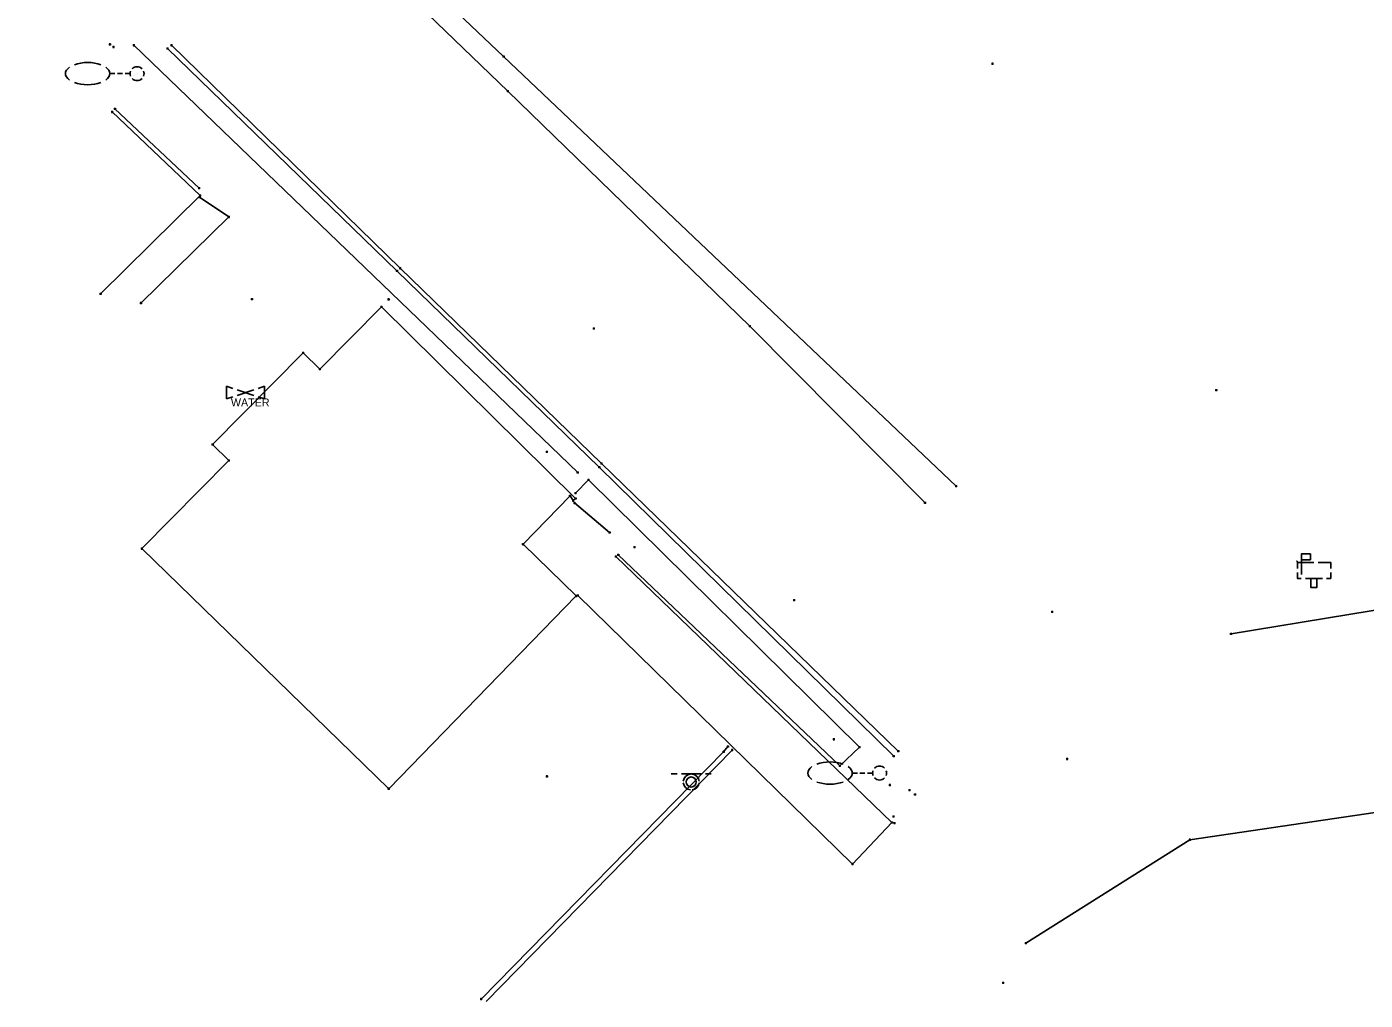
# Model space of a CAD drawing. Extents: x 1954856 to 2011933, y 399149 to 426294.
# Drawn here: x 2005154.1 to 2005312.9, y 406133.7 to 406249.2 of the extents above; entities that cross this region are included whole.
import ezdxf

# ---------------------------------------------------------------- set-up
doc = ezdxf.new("R2010")
doc.units = 0
for name, color, linetype in [('Building_ep', 7, 'Continuous'), ('CGBack_ep', 7, 'Continuous'), ('Driveway_ep', 7, 'Continuous'), ('Fence_ep', 7, 'Continuous'), ('Luminaire_ep', 7, 'Continuous'), ('Mailbox_ep', 7, 'Continuous'), ('PointLocator_ep', 7, 'Continuous'), ('ShrubHedge_ep', 7, 'Continuous'), ('SidewalkFront_ep', 7, 'Continuous'), ('SignSingle_ep', 7, 'Continuous'), ('Stairs_ep', 7, 'Continuous'), ('ValveWater_ep', 7, 'Continuous')]:
    doc.layers.add(name, color=color, linetype=linetype)

# ---------------------------------------------------------------- blocks, each defined once
blk = doc.blocks.new('SURVPN-CROSS-')
at = {"layer": 'PointLocator_ep'}
for p, q in [((0.125, 0), (-0.125, 0)), ((0, -0.125), (0, 0.125)), ((0, 0), (0, 0))]:
    blk.add_line(p, q, dxfattribs=at)

msp = doc.modelspace()

# ---------------------------------------------------------------- linework, layer by layer
at = {"layer": 'Building_ep'}
msp.add_lwpolyline([(2005197.06, 406158.83), (2005219.31, 406181.7), (2005213, 406187.84), (2005218.58, 406193.57), (2005218.95, 406193.02), (2005219.24, 406193.27), (2005196.21, 406216), (2005188.9, 406208.6), (2005186.91, 406210.57), (2005176.16, 406199.68), (2005178.08, 406197.78), (2005167.76, 406187.32)], close=True, dxfattribs=at)
at = {"layer": 'CGBack_ep'}
for p, q in [((2005198.03, 406220.28), (2005170.82, 406246.68)), ((2005164.57, 406239.52), (2005174.58, 406230.08)), ((2005222.05, 406196.98), (2005198.03, 406220.28)), ((2005256.98, 406162.69), (2005222.05, 406196.98))]:
    msp.add_line(p, q, dxfattribs=at)
msp.add_lwpolyline([(2005237.31, 406163.84), (2005236.8, 406163.22), (2005208.02, 406133.88)], dxfattribs=at)
at = {"layer": 'Driveway_ep'}
for p, q in [((2005154.1, 406296.53), (2005211.2, 406241.61)), ((2005198.4, 406220.59), (2005171.28, 406247.05)), ((2005211.2, 406241.61), (2005239.9, 406213.7)), ((2005164.25, 406239.14), (2005174.68, 406229.21)), ((2005174.68, 406229.21), (2005162.87, 406217.56)), ((2005222.31, 406197.43), (2005198.4, 406220.59)), ((2005239.9, 406213.7), (2005260.7, 406192.74)), ((2005257.53, 406163.3), (2005222.31, 406197.43)), ((2005297.01, 406177.21), (2005316.96, 406180.47)), ((2005208.64, 406133.6), (2005237.83, 406163.42)), ((2005317.28, 406156.5), (2005292.13, 406152.78)), ((2005292.13, 406152.78), (2005272.68, 406140.52))]:
    msp.add_line(p, q, dxfattribs=at)
at = {"layer": 'Fence_ep'}
msp.add_lwpolyline([(2005156.64, 406297), (2005210.69, 406245.71), (2005264.38, 406194.73)], dxfattribs=at)
at = {"layer": 'Luminaire_ep'}
for p, q in [((2005164.57, 406243.68), (2005163.97, 406243.68)), ((2005165.47, 406243.68), (2005164.87, 406243.68)), ((2005166.37, 406243.68), (2005165.77, 406243.68)), ((2005167.2, 406243.68), (2005167.2, 406243.68)), ((2005252.67, 406160.69), (2005252.07, 406160.69)), ((2005253.57, 406160.69), (2005252.97, 406160.69)), ((2005254.47, 406160.69), (2005253.87, 406160.69)), ((2005255.3, 406160.69), (2005255.3, 406160.69))]:
    msp.add_line(p, q, dxfattribs=at)
for centre, start, end in [((2005167.2, 406243.68), 159.9115, 200.0885), ((2005167.2, 406243.68), 45, 135), ((2005167.2, 406243.68), 339.9115, 20.0885), ((2005167.2, 406243.68), 225, 315), ((2005255.3, 406160.69), 45, 135), ((2005255.3, 406160.69), 159.9115, 200.0885), ((2005255.3, 406160.69), 225, 315), ((2005255.3, 406160.69), 339.9115, 20.0885)]:
    msp.add_arc(centre, 0.825, start, end, dxfattribs=at)
for centre, start_param, end_param in [((2005161.33, 406243.68), 5.668326, 6.898045), ((2005161.33, 406243.68), 4.075781, 5.348997), ((2005161.33, 406243.68), 2.526733, 3.756452), ((2005161.33, 406243.68), 0.934187, 2.207405), ((2005249.43, 406160.69), 5.668326, 6.898045), ((2005249.43, 406160.69), 4.075781, 5.348997), ((2005249.43, 406160.69), 2.526733, 3.756452), ((2005249.43, 406160.69), 0.934187, 2.207405)]:
    msp.add_ellipse(centre, major_axis=(-2.64, 0), ratio=0.5, start_param=start_param, end_param=end_param, dxfattribs=at)
at = {"layer": 'Mailbox_ep'}
for p, q in [((2005304.9, 406185.69), (2005304.9, 406184.98)), ((2005306.85, 406185.69), (2005304.9, 406185.69)), ((2005305.36, 406184.27), (2005305.36, 406186.01)), ((2005305.36, 406186.01), (2005306.35, 406186.01)), ((2005308.85, 406185.69), (2005308.85, 406184.98)), ((2005305.85, 406183.78), (2005306.35, 406183.78)), ((2005306.35, 406183.78), (2005307.85, 406183.78)), ((2005308.85, 406184.48), (2005308.85, 406183.78)), ((2005306.83, 406182.7), (2005306.83, 406182.7))]:
    msp.add_line(p, q, dxfattribs=at)
for points in [[(2005306.35, 406186.7), (2005305.36, 406186.7), (2005305.36, 406186.01)], [(2005306.35, 406186.01), (2005306.44, 406186.01), (2005306.44, 406186.7), (2005306.35, 406186.7)], [(2005304.78, 406185.82), (2005304.86, 406185.82), (2005304.9, 406185.64)], [(2005308.85, 406185.23), (2005308.85, 406185.69), (2005307.35, 406185.69)], [(2005304.9, 406184.48), (2005304.9, 406183.78), (2005305.35, 406183.78)], [(2005306.49, 406183.78), (2005306.49, 406182.7), (2005307.18, 406182.7), (2005307.18, 406183.78)], [(2005308.35, 406183.78), (2005308.85, 406183.78), (2005308.85, 406184.23)]]:
    msp.add_lwpolyline(points, dxfattribs=at)
at = {"layer": 'PointLocator_ep'}
for p, q in [((2005164.11, 406247.15), (2005163.86, 406247.15)), ((2005163.98, 406247.03), (2005163.98, 406247.28)), ((2005163.98, 406247.15), (2005163.98, 406247.15)), ((2005164.4, 406246.72), (2005164.4, 406246.97)), ((2005166.94, 406247.04), (2005166.69, 406247.04)), ((2005166.82, 406246.91), (2005166.82, 406247.16)), ((2005166.82, 406247.04), (2005166.82, 406247.04)), ((2005171.41, 406247.05), (2005171.16, 406247.05)), ((2005171.28, 406246.92), (2005171.28, 406247.17)), ((2005171.28, 406247.05), (2005171.28, 406247.05)), ((2005164.53, 406246.85), (2005164.28, 406246.85)), ((2005164.4, 406246.85), (2005164.4, 406246.85)), ((2005170.94, 406246.68), (2005170.69, 406246.68)), ((2005170.82, 406246.55), (2005170.82, 406246.8)), ((2005170.82, 406246.68), (2005170.82, 406246.68)), ((2005210.82, 406245.71), (2005210.57, 406245.71)), ((2005210.69, 406245.58), (2005210.69, 406245.83)), ((2005210.69, 406245.71), (2005210.69, 406245.71)), ((2005268.83, 406244.86), (2005268.58, 406244.86)), ((2005268.7, 406244.74), (2005268.7, 406244.99)), ((2005268.7, 406244.86), (2005268.7, 406244.86)), ((2005211.32, 406241.61), (2005211.07, 406241.61)), ((2005211.2, 406241.48), (2005211.2, 406241.73)), ((2005211.2, 406241.61), (2005211.2, 406241.61)), ((2005164.37, 406239.14), (2005164.12, 406239.14)), ((2005164.25, 406239.01), (2005164.25, 406239.26)), ((2005164.25, 406239.14), (2005164.25, 406239.14)), ((2005164.7, 406239.52), (2005164.45, 406239.52)), ((2005164.57, 406239.39), (2005164.57, 406239.64)), ((2005164.57, 406239.52), (2005164.57, 406239.52)), ((2005174.7, 406230.08), (2005174.45, 406230.08)), ((2005174.58, 406229.96), (2005174.58, 406230.21)), ((2005174.58, 406230.08), (2005174.58, 406230.08)), ((2005174.75, 406229.02), (2005174.5, 406229.02)), ((2005174.81, 406229.21), (2005174.56, 406229.21)), ((2005174.62, 406228.9), (2005174.62, 406229.15)), ((2005174.62, 406229.02), (2005174.62, 406229.02)), ((2005174.68, 406229.09), (2005174.68, 406229.34)), ((2005174.68, 406229.21), (2005174.68, 406229.21)), ((2005178.21, 406226.68), (2005177.96, 406226.68)), ((2005178.09, 406226.55), (2005178.09, 406226.8)), ((2005178.09, 406226.68), (2005178.09, 406226.68)), ((2005198.16, 406220.28), (2005197.91, 406220.28)), ((2005198.03, 406220.16), (2005198.03, 406220.41)), ((2005198.03, 406220.28), (2005198.03, 406220.28)), ((2005198.53, 406220.59), (2005198.28, 406220.59)), ((2005198.4, 406220.46), (2005198.4, 406220.71)), ((2005198.4, 406220.59), (2005198.4, 406220.59)), ((2005163, 406217.56), (2005162.75, 406217.56)), ((2005162.87, 406217.43), (2005162.87, 406217.68)), ((2005162.87, 406217.56), (2005162.87, 406217.56)), ((2005180.96, 406216.93), (2005180.71, 406216.93)), ((2005180.83, 406216.8), (2005180.83, 406217.05)), ((2005180.83, 406216.93), (2005180.83, 406216.93)), ((2005197.17, 406216.9), (2005196.92, 406216.9)), ((2005197.04, 406216.78), (2005197.04, 406217.03)), ((2005197.04, 406216.9), (2005197.04, 406216.9)), ((2005167.78, 406216.46), (2005167.53, 406216.46)), ((2005167.66, 406216.34), (2005167.66, 406216.59)), ((2005167.66, 406216.46), (2005167.66, 406216.46)), ((2005196.33, 406216), (2005196.08, 406216)), ((2005196.21, 406215.88), (2005196.21, 406216.13)), ((2005196.21, 406216), (2005196.21, 406216)), ((2005240.03, 406213.7), (2005239.78, 406213.7)), ((2005239.9, 406213.58), (2005239.9, 406213.83)), ((2005239.9, 406213.7), (2005239.9, 406213.7)), ((2005187.03, 406210.57), (2005186.78, 406210.57)), ((2005186.91, 406210.44), (2005186.91, 406210.69)), ((2005186.91, 406210.57), (2005186.91, 406210.57)), ((2005189.02, 406208.6), (2005188.77, 406208.6)), ((2005188.9, 406208.48), (2005188.9, 406208.73)), ((2005188.9, 406208.6), (2005188.9, 406208.6)), ((2005295.39, 406206.12), (2005295.14, 406206.12)), ((2005295.26, 406206), (2005295.26, 406206.25)), ((2005295.26, 406206.12), (2005295.26, 406206.12)), ((2005176.29, 406199.68), (2005176.04, 406199.68)), ((2005176.16, 406199.55), (2005176.16, 406199.8)), ((2005176.16, 406199.68), (2005176.16, 406199.68)), ((2005178.21, 406197.78), (2005177.96, 406197.78)), ((2005178.08, 406197.66), (2005178.08, 406197.91)), ((2005178.08, 406197.78), (2005178.08, 406197.78)), ((2005215.95, 406198.8), (2005215.7, 406198.8)), ((2005215.82, 406198.67), (2005215.82, 406198.92)), ((2005215.82, 406198.8), (2005215.82, 406198.8)), ((2005219.61, 406196.34), (2005219.36, 406196.34)), ((2005219.49, 406196.22), (2005219.49, 406196.47)), ((2005219.49, 406196.34), (2005219.49, 406196.34)), ((2005222.18, 406196.98), (2005221.93, 406196.98)), ((2005222.05, 406196.85), (2005222.05, 406197.1)), ((2005222.05, 406196.98), (2005222.05, 406196.98)), ((2005222.43, 406197.43), (2005222.18, 406197.43)), ((2005222.31, 406197.3), (2005222.31, 406197.55)), ((2005222.31, 406197.43), (2005222.31, 406197.43)), ((2005220.89, 406195.5), (2005220.64, 406195.5)), ((2005220.77, 406195.37), (2005220.77, 406195.62)), ((2005220.77, 406195.5), (2005220.77, 406195.5)), ((2005264.51, 406194.73), (2005264.26, 406194.73)), ((2005264.38, 406194.6), (2005264.38, 406194.85)), ((2005264.38, 406194.73), (2005264.38, 406194.73)), ((2005218.7, 406193.57), (2005218.45, 406193.57)), ((2005218.58, 406193.45), (2005218.58, 406193.7)), ((2005218.58, 406193.57), (2005218.58, 406193.57)), ((2005219.08, 406193.02), (2005218.83, 406193.02)), ((2005218.95, 406192.89), (2005218.95, 406193.14)), ((2005218.95, 406193.02), (2005218.95, 406193.02)), ((2005219.35, 406193.9), (2005219.1, 406193.9)), ((2005219.37, 406193.27), (2005219.12, 406193.27)), ((2005219.23, 406193.78), (2005219.23, 406194.03)), ((2005219.23, 406193.9), (2005219.23, 406193.9)), ((2005219.24, 406193.14), (2005219.24, 406193.39)), ((2005219.24, 406193.27), (2005219.24, 406193.27)), ((2005219.23, 406192.74), (2005218.98, 406192.74)), ((2005219.1, 406192.61), (2005219.1, 406192.86)), ((2005219.1, 406192.74), (2005219.1, 406192.74)), ((2005260.82, 406192.74), (2005260.57, 406192.74)), ((2005260.7, 406192.62), (2005260.7, 406192.87)), ((2005260.7, 406192.74), (2005260.7, 406192.74)), ((2005223.4, 406189.25), (2005223.15, 406189.25)), ((2005223.27, 406189.12), (2005223.27, 406189.37)), ((2005223.27, 406189.25), (2005223.27, 406189.25)), ((2005167.88, 406187.32), (2005167.63, 406187.32)), ((2005167.76, 406187.19), (2005167.76, 406187.44)), ((2005167.76, 406187.32), (2005167.76, 406187.32)), ((2005213.12, 406187.84), (2005212.87, 406187.84)), ((2005213, 406187.71), (2005213, 406187.96)), ((2005213, 406187.84), (2005213, 406187.84)), ((2005224.3, 406186.46), (2005224.3, 406186.71)), ((2005226.35, 406187.48), (2005226.1, 406187.48)), ((2005226.22, 406187.36), (2005226.22, 406187.61)), ((2005226.22, 406187.48), (2005226.22, 406187.48)), ((2005224.13, 406186.38), (2005223.88, 406186.38)), ((2005224.01, 406186.25), (2005224.01, 406186.5)), ((2005224.01, 406186.38), (2005224.01, 406186.38)), ((2005224.43, 406186.58), (2005224.18, 406186.58)), ((2005224.3, 406186.58), (2005224.3, 406186.58)), ((2005219.5, 406181.63), (2005219.5, 406181.88)), ((2005219.43, 406181.7), (2005219.18, 406181.7)), ((2005219.31, 406181.58), (2005219.31, 406181.83)), ((2005219.31, 406181.7), (2005219.31, 406181.7)), ((2005219.62, 406181.75), (2005219.37, 406181.75)), ((2005219.5, 406181.75), (2005219.5, 406181.75)), ((2005245.3, 406181.19), (2005245.05, 406181.19)), ((2005245.18, 406181.07), (2005245.18, 406181.32)), ((2005245.18, 406181.19), (2005245.18, 406181.19)), ((2005275.91, 406179.81), (2005275.66, 406179.81)), ((2005275.79, 406179.69), (2005275.79, 406179.94)), ((2005275.79, 406179.81), (2005275.79, 406179.81)), ((2005297.14, 406177.21), (2005296.89, 406177.21)), ((2005297.01, 406177.08), (2005297.01, 406177.33)), ((2005297.01, 406177.21), (2005297.01, 406177.21)), ((2005249.99, 406164.7), (2005249.74, 406164.7)), ((2005249.86, 406164.57), (2005249.86, 406164.82)), ((2005249.86, 406164.7), (2005249.86, 406164.7)), ((2005236.93, 406163.22), (2005236.68, 406163.22)), ((2005236.8, 406163.09), (2005236.8, 406163.34)), ((2005236.8, 406163.22), (2005236.8, 406163.22)), ((2005237.44, 406163.84), (2005237.19, 406163.84)), ((2005237.31, 406163.71), (2005237.31, 406163.96)), ((2005237.31, 406163.84), (2005237.31, 406163.84)), ((2005237.95, 406163.42), (2005237.7, 406163.42)), ((2005237.83, 406163.3), (2005237.83, 406163.55)), ((2005237.83, 406163.42), (2005237.83, 406163.42)), ((2005253.06, 406163.76), (2005252.81, 406163.76)), ((2005252.93, 406163.64), (2005252.93, 406163.89)), ((2005252.93, 406163.76), (2005252.93, 406163.76)), ((2005256.98, 406162.56), (2005256.98, 406162.81)), ((2005257.66, 406163.3), (2005257.41, 406163.3)), ((2005257.53, 406163.17), (2005257.53, 406163.42)), ((2005257.53, 406163.3), (2005257.53, 406163.3)), ((2005250.72, 406161.55), (2005250.47, 406161.55)), ((2005250.59, 406161.42), (2005250.59, 406161.67)), ((2005250.59, 406161.55), (2005250.59, 406161.55)), ((2005257.1, 406162.69), (2005256.85, 406162.69)), ((2005256.98, 406162.69), (2005256.98, 406162.69)), ((2005215.96, 406160.3), (2005215.71, 406160.3)), ((2005215.83, 406160.18), (2005215.83, 406160.43)), ((2005215.83, 406160.3), (2005215.83, 406160.3)), ((2005197.18, 406158.83), (2005196.93, 406158.83)), ((2005197.06, 406158.71), (2005197.06, 406158.96)), ((2005197.06, 406158.83), (2005197.06, 406158.83)), ((2005256.66, 406159.27), (2005256.41, 406159.27)), ((2005256.53, 406159.15), (2005256.53, 406159.4)), ((2005256.53, 406159.27), (2005256.53, 406159.27)), ((2005258.98, 406158.67), (2005258.73, 406158.67)), ((2005258.86, 406158.54), (2005258.86, 406158.79)), ((2005258.86, 406158.67), (2005258.86, 406158.67)), ((2005259.64, 406158.16), (2005259.39, 406158.16)), ((2005259.52, 406158.03), (2005259.52, 406158.28)), ((2005259.52, 406158.16), (2005259.52, 406158.16)), ((2005256.78, 406154.69), (2005256.78, 406154.94)), ((2005257.07, 406155.52), (2005256.82, 406155.52)), ((2005256.95, 406155.4), (2005256.95, 406155.65)), ((2005256.95, 406155.52), (2005256.95, 406155.52)), ((2005257.07, 406154.61), (2005257.07, 406154.86)), ((2005256.91, 406154.81), (2005256.66, 406154.81)), ((2005256.78, 406154.81), (2005256.78, 406154.81)), ((2005257.19, 406154.74), (2005256.94, 406154.74)), ((2005257.07, 406154.74), (2005257.07, 406154.74)), ((2005292.25, 406152.78), (2005292, 406152.78)), ((2005292.13, 406152.66), (2005292.13, 406152.91)), ((2005292.13, 406152.78), (2005292.13, 406152.78)), ((2005252.23, 406149.89), (2005251.98, 406149.89)), ((2005252.11, 406149.77), (2005252.11, 406150.02)), ((2005252.11, 406149.89), (2005252.11, 406149.89)), ((2005272.68, 406140.39), (2005272.68, 406140.64)), ((2005272.8, 406140.52), (2005272.55, 406140.52)), ((2005272.68, 406140.52), (2005272.68, 406140.52)), ((2005270.11, 406135.8), (2005269.86, 406135.8)), ((2005269.99, 406135.67), (2005269.99, 406135.92)), ((2005269.99, 406135.8), (2005269.99, 406135.8)), ((2005208.14, 406133.88), (2005207.89, 406133.88)), ((2005208.02, 406133.75), (2005208.02, 406134)), ((2005208.02, 406133.88), (2005208.02, 406133.88))]:
    msp.add_line(p, q, dxfattribs=at)
at = {"layer": 'ShrubHedge_ep'}
msp.add_lwpolyline([(2005219.49, 406196.34), (2005166.82, 406247.04)], dxfattribs=at)
at = {"layer": 'SidewalkFront_ep'}
for points in [[(2005174.62, 406229.02), (2005178.09, 406226.68), (2005167.66, 406216.46)], [(2005224.01, 406186.38), (2005256.78, 406154.81)], [(2005256.78, 406154.81), (2005252.11, 406149.89), (2005219.5, 406181.75)]]:
    msp.add_lwpolyline(points, dxfattribs=at)
at = {"layer": 'SignSingle_ep'}
for p, q in [((2005230.59, 406160.58), (2005231.29, 406160.58)), ((2005231.79, 406160.58), (2005234.14, 406160.58)), ((2005232.96, 406159.63), (2005232.96, 406159.63)), ((2005234.64, 406160.58), (2005235.34, 406160.58))]:
    msp.add_line(p, q, dxfattribs=at)
msp.add_circle((2005232.96, 406159.63), 0.594, dxfattribs=at)
for start, end in [(96.0423, 173.9577), (6.0423, 83.9577), (186.0423, 263.9577), (276.0423, 353.9577)]:
    msp.add_arc((2005232.96, 406159.63), 0.95, start, end, dxfattribs=at)
at = {"layer": 'Stairs_ep'}
for points in [[(2005224.3, 406186.58), (2005250.59, 406161.55), (2005252.93, 406163.76), (2005220.77, 406195.5), (2005219.23, 406193.9)], [(2005219.1, 406192.74), (2005223.27, 406189.25)]]:
    msp.add_lwpolyline(points, dxfattribs=at)
at = {"layer": 'ValveWater_ep'}
for p, q in [((2005178.57, 406206.33), (2005177.82, 406206.58)), ((2005177.82, 406205.08), (2005177.82, 406206.58)), ((2005181.07, 406205.5), (2005179.07, 406206.17)), ((2005179.07, 406205.5), (2005181.07, 406206.17)), ((2005180.07, 406205.83), (2005180.07, 406205.83)), ((2005181.57, 406206.33), (2005182.32, 406206.58)), ((2005182.32, 406206.58), (2005182.32, 406205.08)), ((2005177.82, 406205.08), (2005178.57, 406205.33)), ((2005182.32, 406205.08), (2005181.57, 406205.33))]:
    msp.add_line(p, q, dxfattribs=at)

# ---------------------------------------------------------------- block references
at = {"layer": 'PointLocator_ep'}
for p in [(2005221.41, 406213.44), (2005277.58, 406162.36)]:
    msp.add_blockref('SURVPN-CROSS-', p, dxfattribs=at)

# ---------------------------------------------------------------- texts
at = {"layer": 'ValveWater_ep'}
msp.add_text('WATER', height=0.95, dxfattribs=at).set_placement((2005178.33, 406204.19))

doc.saveas('drawing.dxf')
